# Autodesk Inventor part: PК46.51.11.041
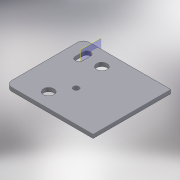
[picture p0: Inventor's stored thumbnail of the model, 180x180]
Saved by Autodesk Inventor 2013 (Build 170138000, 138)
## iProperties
Shininess: 64.0
Length Units: 11269
Angle Units: 11279
Time Units: 11290
Mass Units: 11283
Length Display Precision: 3
Angle Display Precision: 2
Compacted: True
Part Number: PК46.51.11.041
Document SubType Name: Листовой материал
Created: 2005-02
Material: Steel, Mild
Designer: =<Author>
Manufacturer: Standard
Standards Organization: Custom
Description: Reliance Lock
Density: 7.86 g/cm^3
Sheet Metal Rule: По умолчанию
Mass: 215.425 g
Surface Area: 155.597 cm^2
Volume: 27.4078 cm^3
Density: 0.0
Volumn: 0.0
Area: 0.0
PropertySet Name: Model Information
Control State: 0
Master: False
Checked Out: False
Checked Out Date: 2008-10-15
Last Check In Date: 2008-10-15
Толщина: 4.000 mm
Радиус_гибки: 4.000 mm
Ширина_просечки: 4.000 mm
Глубина_просечки: 2.000 mm
Размер_высечки: 16.000 mm
Минимальный_остаток: 8.000 mm
Радиус_перехода: 4.000 mm
JacobiRadiusSize: 4.000 mm
GapSize: 4.000 mm
d0: 80.000 mm
d1: 90.000 mm
d2: 15.000 mm
d4: 5.000 mm
d5: 50.000 mm
d6: 11.000 mm
d7: 4.000 mm
d8: 8.000 mm
d10: 8.000 mm
d11: 6.000 mm
d12: 25.000 mm
d14: 28.000 mm
d15: 3.500 mm
d16: 29.000 mm
d17: 19.000 mm
d31: 6.000 mm
Author: PVitaliy
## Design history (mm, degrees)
node "Грань1"
node "РабПлоскость1"
feature "УглСкругление1" dims "d31" = 6
body "Solid1"
sketch "Эскиз1"
  geometry: L1 (0, 0)-(90, 0); L2 (90, 0)-(90, 80); L3 (90, 80)-(0, 80); L4 (0, 80)-(0, 0); L5 (15, 68.5)-(15, 60.5); L6 (19, 68.5)-(19, 60.5); L7 (11, 68.5)-(11, 60.5); C1 r 5.5 at (34, 65); C2 r 5.5 at (29, 15); C3 r 3 at (40, 32.5); A1 r 4 centre (15, 68.5) between (19, 68.5) and (11, 68.5); A2 r 4 centre (15, 60.5) between (11, 60.5) and (19, 60.5)
  constraints: 14 end point, 5 centre point, 4 parallel, 4 point on circle, 3 tangent, 2 equal radius, 1 coincident, 1 horizontal, 1 perpendicular, 1 other
  dimensions: "d0" = 80 distance of L3.end L1.start; "d1" = 90 distance of L1.start L1.end; "d2" = 15 distance from line of L3 C1.centre; "d4" = 5 horizontal distance of C2.centre C1.centre; "d5" = 50 vertical distance of C2.centre C1.centre; "d6" = 11 diameter of C1; "d8" = 8 distance of L5.start L5.end; "d10" = 8 distance between parallel lines of L7 L6; "d11" = 6 diameter of C3; "d12" = 25 distance from line of C3.centre L5; "d14" = 28 vertical distance of C3.centre A2.centre; "d15" = 3.5 vertical distance of L5.start C1.centre; "d16" = 29 distance from line of C2.centre L4; "d17" = 19 distance from line of C1.centre L5
feature "Пластина1" dims "Толщина" = 4
other parameters: "Радиус_гибки" = 4 (= Толщина), "Ширина_просечки" = 4 (= Толщина), "Глубина_просечки" = 2 (= 0.5 x Толщина), "Размер_высечки" = 16 (= 4 x Толщина), "Зазор_стыка" = 0.01, "Минимальный_остаток" = 8 (= 2 x Толщина), "Радиус_перехода" = 4 (= Радиус_гибки), "d7" = 4 (= Радиус_гибки), "JacobiRadiusSize" = 4 (= Толщина), "GapSize" = 4 (= Толщина)
